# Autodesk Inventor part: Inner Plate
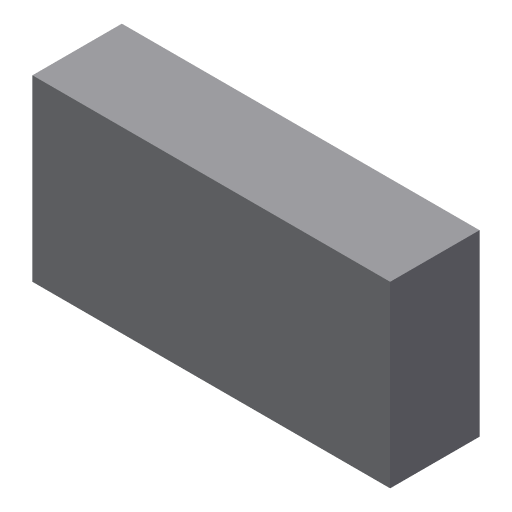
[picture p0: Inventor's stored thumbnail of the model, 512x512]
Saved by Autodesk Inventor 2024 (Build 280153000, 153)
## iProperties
Created: 2010-04
Part Number: Inner Plate
Document SubType Name: Modeling
Designer: CADSoft
Density: 1 g/cm^3
Material: Generic
Appearance: Default
Author: CADSoft
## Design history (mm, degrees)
sketch "Sketch1"
  geometry: L1 (-20.23, -7.511)-(19.77, -7.511); L2 (19.77, -7.511)-(19.77, 12.489); L3 (19.77, 12.489)-(-20.23, 12.489); L4 (-20.23, 12.489)-(-20.23, -7.511); 1 further point
  constraints: 8 end point, 2 parallel, 1 horizontal, 1 perpendicular
workplane "Work Plane1"
extrude "Extrusion1" new body sketch "Sketch1" stored distance "d0" = 25.4; taper "d1" = 0 deg
body "Solid1"
